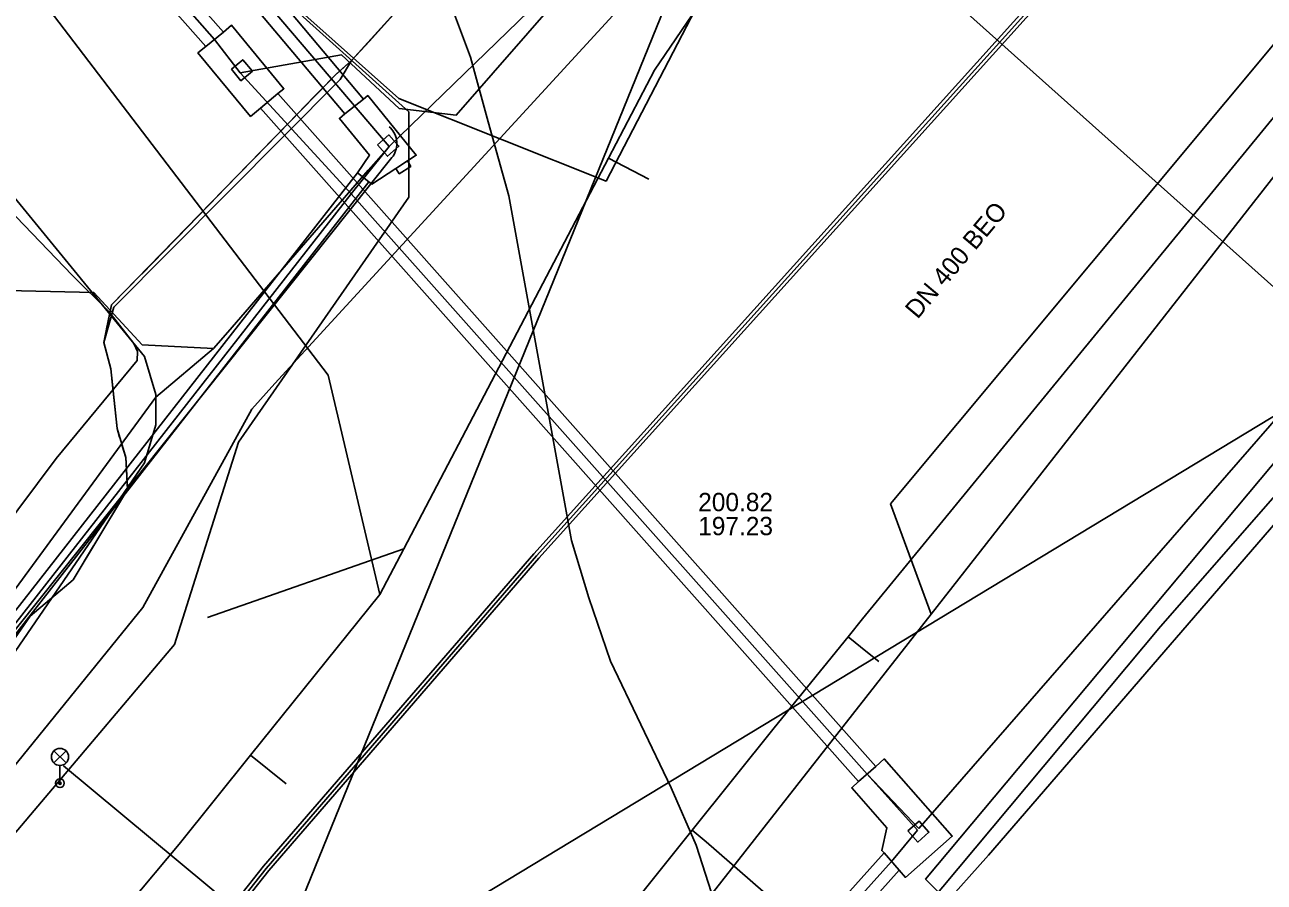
# Model space of a CAD drawing. Extents: x -598932 to -598196, y -1162210 to -1161504.
# Drawn here: x -598627.1 to -598572.9, y -1161789 to -1161751.5 of the extents above; entities that cross this region are included whole.
import ezdxf

# ---------------------------------------------------------------- set-up
doc = ezdxf.new("R2010")
doc.units = 0
for name, color, linetype in [('Vrstva 1', 7, 'Continuous'), ('Vrstva 10', 7, 'Continuous'), ('Vrstva 12', 7, 'Continuous'), ('Vrstva 13', 7, 'Continuous'), ('Vrstva 14', 7, 'Continuous'), ('Vrstva 16', 7, 'Continuous'), ('Vrstva 33', 7, 'Continuous'), ('Vrstva 4', 7, 'Continuous'), ('Vrstva 42', 7, 'Continuous'), ('Vrstva 44', 7, 'Continuous'), ('Vrstva 53', 7, 'Continuous'), ('Vrstva 54', 7, 'Continuous'), ('Vrstva 55', 7, 'Continuous'), ('Vrstva 58', 7, 'Continuous'), ('Vrstva 9', 7, 'Continuous')]:
    doc.layers.add(name, color=color, linetype=linetype)

msp = doc.modelspace()

# ---------------------------------------------------------------- linework, layer by layer
at = {"layer": 'Vrstva 1'}
for p, q in [((-598570.08, -1161749.41), (-598589.26, -1161772.42)), ((-598589.26, -1161772.42), (-598587.489, -1161777.24)), ((-598619.154, -1161777.396), (-598610.566, -1161774.388))]:
    msp.add_line(p, q, dxfattribs=at)
at = {"layer": 'Vrstva 10'}
for p, q in [((-598648.42, -1161711.89), (-598612.32, -1161754.71)), ((-598648.42, -1161711.89), (-598612.32, -1161754.71)), ((-598649.44, -1161712.32), (-598613.14, -1161755.36)), ((-598649.44, -1161712.32), (-598613.14, -1161755.36)), ((-598638.16, -1161729.41), (-598618.46, -1161751.78)), ((-598638.16, -1161729.41), (-598618.46, -1161751.78)), ((-598639.01, -1161729.96), (-598619.23, -1161752.41)), ((-598639.01, -1161729.96), (-598619.23, -1161752.41)), ((-598619.23, -1161752.41), (-598618.46, -1161751.78)), ((-598619.23, -1161752.41), (-598618.46, -1161751.78)), ((-598616.84, -1161755.11), (-598616.07, -1161754.47)), ((-598616.84, -1161755.11), (-598616.07, -1161754.47)), ((-598616.07, -1161754.47), (-598589.91, -1161783.91)), ((-598616.07, -1161754.47), (-598589.91, -1161783.91)), ((-598613.14, -1161755.36), (-598612.32, -1161754.71)), ((-598613.14, -1161755.36), (-598612.32, -1161754.71)), ((-598616.84, -1161755.11), (-598590.66, -1161784.57)), ((-598616.84, -1161755.11), (-598590.66, -1161784.57)), ((-598610.91, -1161757.75), (-598610.4, -1161757.42)), ((-598610.91, -1161757.75), (-598610.4, -1161757.42)), ((-598639.29, -1161792.09), (-598612.59, -1161757.94)), ((-598639.29, -1161792.09), (-598612.59, -1161757.94)), ((-598612.59, -1161757.94), (-598612.09, -1161758.33)), ((-598612.59, -1161757.94), (-598612.09, -1161758.33)), ((-598638.76, -1161792.44), (-598612.09, -1161758.33)), ((-598638.76, -1161792.44), (-598612.09, -1161758.33)), ((-598590.66, -1161784.57), (-598589.91, -1161783.91)), ((-598590.66, -1161784.57), (-598589.91, -1161783.91)), ((-598625.29, -1161827.53), (-598589.54, -1161787.69)), ((-598625.29, -1161827.53), (-598589.54, -1161787.69)), ((-598589.54, -1161787.69), (-598588.89, -1161788.45)), ((-598589.54, -1161787.69), (-598588.89, -1161788.45)), ((-598624.5, -1161828.14), (-598588.89, -1161788.45)), ((-598624.5, -1161828.14), (-598588.89, -1161788.45))]:
    msp.add_line(p, q, dxfattribs=at)
for points in [[(-598616.07, -1161754.47), (-598615.81, -1161754.26), (-598618.1, -1161751.48), (-598618.46, -1161751.78)], [(-598616.07, -1161754.47), (-598615.81, -1161754.26), (-598618.1, -1161751.48), (-598618.46, -1161751.78)], [(-598616.84, -1161755.11), (-598617.27, -1161755.47), (-598619.57, -1161752.69), (-598619.23, -1161752.41)], [(-598616.84, -1161755.11), (-598617.27, -1161755.47), (-598619.57, -1161752.69), (-598619.23, -1161752.41)], [(-598618.11, -1161753.41), (-598617.61, -1161752.99), (-598617.19, -1161753.49), (-598617.69, -1161753.91), (-598618.11, -1161753.41)], [(-598618.11, -1161753.41), (-598617.61, -1161752.99), (-598617.19, -1161753.49), (-598617.69, -1161753.91), (-598618.11, -1161753.41)], [(-598612.32, -1161754.71), (-598612.14, -1161754.56), (-598610.02, -1161757.17), (-598610.4, -1161757.42)], [(-598612.32, -1161754.71), (-598612.14, -1161754.56), (-598610.02, -1161757.17), (-598610.4, -1161757.42)], [(-598613.14, -1161755.36), (-598613.38, -1161755.56), (-598612.07, -1161757.17), (-598612.59, -1161757.94)], [(-598613.14, -1161755.36), (-598613.38, -1161755.56), (-598612.07, -1161757.17), (-598612.59, -1161757.94)], [(-598611.72, -1161756.72), (-598611.28, -1161757.21), (-598610.78, -1161756.77), (-598611.22, -1161756.28), (-598611.72, -1161756.72)], [(-598611.72, -1161756.72), (-598611.28, -1161757.21), (-598610.78, -1161756.77), (-598611.22, -1161756.28), (-598611.72, -1161756.72)], [(-598610.4, -1161757.42), (-598610.26, -1161757.66), (-598610.76, -1161757.98), (-598610.91, -1161757.75)], [(-598610.4, -1161757.42), (-598610.26, -1161757.66), (-598610.76, -1161757.98), (-598610.91, -1161757.75)], [(-598612.09, -1161758.33), (-598611.96, -1161758.43), (-598610.91, -1161757.75)], [(-598612.09, -1161758.33), (-598611.96, -1161758.43), (-598610.91, -1161757.75)], [(-598589.91, -1161783.91), (-598589.54, -1161783.58), (-598586.56, -1161786.96), (-598588.61, -1161788.76), (-598588.89, -1161788.45)], [(-598589.91, -1161783.91), (-598589.54, -1161783.58), (-598586.56, -1161786.96), (-598588.61, -1161788.76), (-598588.89, -1161788.45)], [(-598590.66, -1161784.57), (-598590.96, -1161784.84), (-598589.42, -1161786.6), (-598589.65, -1161787.59), (-598589.54, -1161787.69)], [(-598590.66, -1161784.57), (-598590.96, -1161784.84), (-598589.42, -1161786.6), (-598589.65, -1161787.59), (-598589.54, -1161787.69)], [(-598588.5, -1161786.73), (-598588.07, -1161787.22), (-598587.58, -1161786.79), (-598588.01, -1161786.3), (-598588.5, -1161786.73)], [(-598588.5, -1161786.73), (-598588.07, -1161787.22), (-598587.58, -1161786.79), (-598588.01, -1161786.3), (-598588.5, -1161786.73)]]:
    msp.add_lwpolyline(points, dxfattribs=at)
at = {"layer": 'Vrstva 12'}
for p, q in [((-598611.21, -1161756.79), (-598644.24, -1161717.96)), ((-598618.85, -1161752.1), (-598617.73, -1161753.57)), ((-598617.73, -1161753.57), (-598612.86, -1161758.86)), ((-598560.27, -1161754.79), (-598588.02, -1161786.62)), ((-598612.86, -1161758.86), (-598590.29, -1161784.24)), ((-598590.29, -1161784.24), (-598588.09, -1161786.7)), ((-598590.29, -1161784.24), (-598588.02, -1161786.62))]:
    msp.add_line(p, q, dxfattribs=at)
for points in [[(-598617.73, -1161753.57), (-598613.29, -1161752.78), (-598610.76, -1161755.12), (-598608.27, -1161755.41), (-598576.7, -1161719.3), (-598550.29, -1161690.77), (-598547.14, -1161687.36)], [(-598639.8, -1161728.29), (-598638.6, -1161729.7), (-598618.85, -1161752.1)], [(-598611.21, -1161756.79), (-598612.12, -1161757.82), (-598618.27, -1161764.91), (-598618.89, -1161765.62)], [(-598612.86, -1161758.86), (-598612.32, -1161758.18), (-598611.21, -1161756.79)], [(-598640.35, -1161794.18), (-598638.99, -1161792.25), (-598612.86, -1161758.86)], [(-598618.89, -1161765.62), (-598622.01, -1161765.47), (-598624.13, -1161763.18), (-598633.65, -1161762.95), (-598639.12, -1161764.44), (-598641.01, -1161764.25), (-598642.56, -1161765.55), (-598642.41, -1161767.52), (-598642.41, -1161775.34), (-598642.17, -1161790.19), (-598649.69, -1161797.54), (-598651.68, -1161795.52), (-598698.16, -1161842.5), (-598698.36, -1161842.27)], [(-598641.69, -1161795.86), (-598641.14, -1161794.65), (-598621.42, -1161767.75), (-598618.89, -1161765.62)], [(-598588.09, -1161786.7), (-598589.215, -1161788.07), (-598624.9, -1161827.84)]]:
    msp.add_lwpolyline(points, dxfattribs=at)
at = {"layer": 'Vrstva 13'}
msp.add_lwpolyline([(-598555.27, -1161753.75), (-598583.9, -1161729.43), (-598592.85, -1161739), (-598611.21, -1161756.79)], dxfattribs=at)
at = {"layer": 'Vrstva 14'}
msp.add_line((-598597.949, -1161786.696), (-598597.334, -1161787.209), dxfattribs=at)
for points in [[(-598597.949, -1161786.696), (-598594.355, -1161782.22), (-598591.124, -1161778.235), (-598590.488, -1161777.45), (-598568.259, -1161750.324), (-598540.145, -1161717.756), (-598494.895, -1161668.814), (-598474.946, -1161646.048), (-598446.726, -1161616.22), (-598420.512, -1161586.879), (-598391.532, -1161555.529), (-598341.416, -1161505.182)], [(-598589.947, -1161792.741), (-598577.445, -1161777.792), (-598565.596, -1161764.237), (-598559.546, -1161757.337), (-598558.635, -1161756.275), (-598558.918, -1161751.624), (-598555.314, -1161747.837), (-598550.53, -1161742.727), (-598537.985, -1161729.402), (-598525.355, -1161715.849), (-598512.719, -1161702.199), (-598500.184, -1161688.704), (-598495.944, -1161684.141), (-598496.644, -1161675.242), (-598493.647, -1161671.551), (-598491.273, -1161668.615), (-598474.912, -1161650.419), (-598466.442, -1161641.794), (-598445.99, -1161619.606), (-598438.518, -1161611.629), (-598437.483, -1161610.512)], [(-598714.198, -1161898.74), (-598714.06, -1161898.556), (-598710.961, -1161889.776), (-598709.348, -1161885.209), (-598692.94, -1161864.74), (-598688.776, -1161860.738), (-598685, -1161855.44), (-598662.12, -1161826.49), (-598647.66, -1161808.72), (-598629.293, -1161785.959), (-598621.98, -1161776.96), (-598617.208, -1161768.282), (-598616.2, -1161767.15), (-598599.603, -1161749.072), (-598591.333, -1161740.194), (-598580.26, -1161728.311)], [(-598591.124, -1161778.235), (-598590.275, -1161778.926), (-598589.772, -1161779.324)], [(-598597.949, -1161786.696), (-598602.338, -1161792.178), (-598603.707, -1161793.87)], [(-598597.334, -1161787.209), (-598590.41, -1161793.23), (-598589.947, -1161792.741)]]:
    msp.add_lwpolyline(points, dxfattribs=at)
at = {"layer": 'Vrstva 16'}
msp.add_lwpolyline([(-598560.67, -1161752.75), (-598557.52, -1161756.02), (-598568.8, -1161769.07), (-598584.98, -1161787.79), (-598587.03, -1161790.09), (-598589.52, -1161793.04), (-598597.01, -1161801.89), (-598611.83, -1161819.43), (-598616.42, -1161824.71), (-598624.01, -1161833.48), (-598624.6, -1161833.51)], dxfattribs=at)
at = {"layer": 'Vrstva 33'}
for p, q in [((-598625.874, -1161783.227), (-598625.344, -1161783.757)), ((-598625.874, -1161783.757), (-598625.344, -1161783.227)), ((-598625.609, -1161784.642), (-598625.609, -1161783.867))]:
    msp.add_line(p, q, dxfattribs=at)
for centre, radius in [((-598625.609, -1161783.492), 0.375), ((-598625.609, -1161784.642), 0.19), ((-598625.609, -1161784.642), 0.05)]:
    msp.add_circle(centre, radius, dxfattribs=at)
at = {"layer": 'Vrstva 42'}
msp.add_line((-598640.42, -1161794.02), (-598611.08, -1161757.27), dxfattribs=at)
for points in [[(-598482.625, -1161640.144), (-598482.467, -1161640.638), (-598493.794, -1161653.11), (-598495.271, -1161654.682), (-598509.79, -1161670.452), (-598509.789, -1161670.451), (-598514.544, -1161675.66), (-598514.586, -1161675.706), (-598563.469, -1161729.131), (-598604.648, -1161774.799), (-598616.464, -1161788.466), (-598628.603, -1161803.794)], [(-598628.837, -1161803.606), (-598616.696, -1161788.274), (-598604.872, -1161774.601), (-598563.691, -1161728.929), (-598514.958, -1161675.668), (-598514.766, -1161675.458), (-598510.011, -1161670.249), (-598510.01, -1161670.248), (-598495.509, -1161654.498), (-598494.886, -1161653.538)], [(-598628.837, -1161803.606), (-598616.696, -1161788.274), (-598604.872, -1161774.601), (-598563.691, -1161728.929), (-598514.958, -1161675.668), (-598514.766, -1161675.458), (-598510.011, -1161670.249), (-598510.01, -1161670.248), (-598495.509, -1161654.498), (-598494.886, -1161653.538)], [(-598722.434, -1161887.506), (-598721.303, -1161887.465), (-598711.981, -1161877.933), (-598701.016, -1161865.728), (-598698.292, -1161862.397), (-598697.293, -1161861.83), (-598689.452, -1161859.77), (-598688.12, -1161859.789), (-598687.331, -1161860.531), (-598681.484, -1161865.606), (-598680.195, -1161866.255), (-598678.811, -1161865.236), (-598675.692, -1161860.773), (-598673.236, -1161858.028), (-598665.054, -1161848.125), (-598640.034, -1161817.645), (-598628.603, -1161803.794), (-598616.464, -1161788.466), (-598604.648, -1161774.799), (-598563.469, -1161729.131), (-598514.586, -1161675.706), (-598514.881, -1161675.495)], [(-598514.841, -1161675.57), (-598514.772, -1161675.687), (-598563.58, -1161729.03), (-598604.76, -1161774.7), (-598616.58, -1161788.37), (-598628.72, -1161803.7), (-598640.15, -1161817.55), (-598650.17, -1161829.78), (-598665.17, -1161848.03), (-598673.35, -1161857.93), (-598675.81, -1161860.68), (-598678.92, -1161865.13), (-598680.21, -1161866.08), (-598681.4, -1161865.48), (-598687.23, -1161860.42), (-598688.06, -1161859.64), (-598689.47, -1161859.62), (-598697.35, -1161861.69), (-598698.39, -1161862.28), (-598701.13, -1161865.63), (-598712.09, -1161877.83), (-598721.41, -1161887.36)], [(-598611.08, -1161757.27), (-598611.031, -1161757.203), (-598610.988, -1161757.131), (-598610.951, -1161757.057), (-598610.92, -1161756.979), (-598610.896, -1161756.9), (-598610.88, -1161756.818), (-598610.87, -1161756.735), (-598610.867, -1161756.652), (-598610.872, -1161756.569), (-598610.883, -1161756.486), (-598610.902, -1161756.405), (-598610.927, -1161756.326), (-598610.959, -1161756.249), (-598610.998, -1161756.175), (-598611.042, -1161756.104), (-598611.093, -1161756.038), (-598611.149, -1161755.977), (-598611.21, -1161755.92)]]:
    msp.add_lwpolyline(points, dxfattribs=at)
at = {"layer": 'Vrstva 44'}
msp.add_lwpolyline([(-598629.97, -1161776.02), (-598625.78, -1161770.44), (-598622.23, -1161766.15), (-598622.22, -1161765.76), (-598622.38, -1161765.41), (-598623.47, -1161764), (-598625.08, -1161762.41), (-598628.94, -1161758.4)], dxfattribs=at)
at = {"layer": 'Vrstva 53'}
for points in [[(-598609.61, -1161747.61), (-598607.64, -1161752.88), (-598606.87, -1161755.71), (-598605.97, -1161758.94), (-598603.23, -1161774.02), (-598602.46, -1161776.53), (-598601.52, -1161779.31), (-598598.86, -1161784.84), (-598597.77, -1161787.35), (-598596.71, -1161790.67), (-598595.79, -1161793.54), (-598594.83, -1161796.22), (-598593.94, -1161799.41), (-598592.99, -1161801.85), (-598591.22, -1161806.87), (-598589.7, -1161809.75), (-598588.76, -1161814.1), (-598588.73, -1161814.4)], [(-598609.841, -1161749.701), (-598612.07, -1161752.18), (-598612.85, -1161753.03), (-598613.52, -1161753.62), (-598623.35, -1161763.72), (-598623.69, -1161765.36), (-598623.39, -1161766.52), (-598623.11, -1161769.13), (-598622.73, -1161770.39), (-598622.65, -1161771.79), (-598625.03, -1161775.74), (-598626.92, -1161777.34), (-598629.01, -1161780.33), (-598632.04, -1161785.05), (-598632.43, -1161785.95), (-598634.19, -1161788.81), (-598640.81, -1161797.29)]]:
    msp.add_lwpolyline(points, dxfattribs=at)
at = {"layer": 'Vrstva 54'}
for p, q in [((-598568.721, -1161766.31), (-598595.679, -1161742.213)), ((-598600.402, -1161804.695), (-598625.45, -1161783.876))]:
    msp.add_line(p, q, dxfattribs=at)
for points in [[(-598687.821, -1161859.742), (-598647.718, -1161830.151), (-598630.44, -1161809.067), (-598615.881, -1161791.862), (-598595.724, -1161742.271)], [(-598663.206, -1161879.566), (-598645.593, -1161831.834), (-598628.289, -1161810.908), (-598613.766, -1161793.569), (-598568.721, -1161766.31)]]:
    msp.add_lwpolyline(points, dxfattribs=at)
at = {"layer": 'Vrstva 55'}
for points in [[(-598593.724, -1161815.599), (-598601.79, -1161825.2), (-598612.66, -1161816.58), (-598605.21, -1161808.89), (-598597.75, -1161800.73), (-598596.12, -1161801.43), (-598593.55, -1161803.29), (-598583.76, -1161792.8), (-598587.73, -1161788.84), (-598556.49, -1161751.54), (-598543.66, -1161733.82), (-598504.5, -1161691.15), (-598500.07, -1161684.86), (-598483.28, -1161665.74), (-598469.525, -1161651.138), (-598469.135, -1161651.28), (-598469.525, -1161651.138), (-598431.76, -1161609.32), (-598365.821, -1161539.037), (-598342.93, -1161515.615), (-598331.661, -1161505.182)], [(-598687.9, -1161859.88), (-598687.665, -1161860.067), (-598686.34, -1161858.55), (-598665.36, -1161832.2), (-598647.88, -1161811.69), (-598632.26, -1161792.34), (-598620.6, -1161778.58), (-598617.8, -1161769.72), (-598610.34, -1161759), (-598610.34, -1161755.27), (-598623.936, -1161743.039), (-598634.82, -1161725.89), (-598648.11, -1161713.3), (-598648.437, -1161712.771), (-598653, -1161709.34), (-598656.27, -1161705.61), (-598668.62, -1161681.83), (-598671.66, -1161674.83), (-598683.11, -1161642.61), (-598670.09, -1161637.1), (-598667.406, -1161636.169), (-598667.557, -1161635.626)], [(-598593.724, -1161815.599), (-598601.79, -1161825.2), (-598612.66, -1161816.58), (-598614.54, -1161818.45), (-598638.67, -1161800.34), (-598641.16, -1161798.68), (-598621.91, -1161770.62), (-598621.41, -1161768.96), (-598621.41, -1161767.63), (-598621.91, -1161765.97), (-598661.59, -1161717.49), (-598653.12, -1161709.36), (-598656.44, -1161705.37), (-598668.39, -1161682.46), (-598671.71, -1161674.66), (-598683.11, -1161642.61), (-598670.09, -1161637.1), (-598667.406, -1161636.169), (-598667.557, -1161635.626)], [(-598635.02, -1161725.8), (-598623.513, -1161743.463), (-598608.12, -1161722.98), (-598608.22, -1161717.163), (-598608.12, -1161722.98), (-598623.249, -1161743.568), (-598610.78, -1161754.69), (-598601.71, -1161758.3), (-598595.65, -1161746.64), (-598593.576, -1161744.441), (-598595.719, -1161742.325), (-598593.576, -1161744.441), (-598591.036, -1161741.822), (-598575.14, -1161725.19), (-598564.458, -1161715.417), (-598553.451, -1161703.881), (-598547.789, -1161697.531), (-598546.625, -1161695.044), (-598548.56, -1161692.55), (-598559.49, -1161681.15), (-598556.019, -1161677.263), (-598556.805, -1161676.476)]]:
    msp.add_lwpolyline(points, dxfattribs=at)
at = {"layer": 'Vrstva 58'}
for p, q in [((-598610.196, -1161750.093), (-598612.85, -1161753.03)), ((-598612.85, -1161753.03), (-598611.685, -1161751.741)), ((-598613.52, -1161753.62), (-598612.85, -1161753.03)), ((-598612.85, -1161753.03), (-598613.482, -1161753.586)), ((-598615.033, -1161755.175), (-598613.52, -1161753.62)), ((-598613.763, -1161753.87), (-598615.045, -1161755.186)), ((-598618.392, -1161758.626), (-598615.045, -1161755.186)), ((-598615.045, -1161755.186), (-598617.111, -1161757.31)), ((-598617.122, -1161757.321), (-598618.392, -1161758.626)), ((-598622.019, -1161762.353), (-598618.671, -1161758.913)), ((-598618.671, -1161758.913), (-598620.47, -1161760.761)), ((-598618.392, -1161758.626), (-598618.671, -1161758.913)), ((-598620.749, -1161761.048), (-598622.019, -1161762.353)), ((-598622.019, -1161762.353), (-598622.03, -1161762.364)), ((-598623.35, -1161763.72), (-598622.03, -1161762.364)), ((-598622.03, -1161762.364), (-598623.35, -1161763.72)), ((-598623.69, -1161765.36), (-598623.35, -1161763.72)), ((-598623.35, -1161763.72), (-598623.567, -1161764.768)), ((-598623.571, -1161764.784), (-598623.69, -1161765.36)), ((-598623.39, -1161766.52), (-598623.69, -1161765.36)), ((-598623.69, -1161765.36), (-598623.39, -1161766.52)), ((-598623.39, -1161766.52), (-598623.11, -1161769.13)), ((-598623.11, -1161769.13), (-598623.344, -1161766.952)), ((-598622.73, -1161770.39), (-598623.11, -1161769.13)), ((-598623.11, -1161769.13), (-598622.998, -1161769.502)), ((-598622.882, -1161769.885), (-598622.73, -1161770.39)), ((-598622.656, -1161771.682), (-598622.73, -1161770.39)), ((-598622.73, -1161770.39), (-598622.65, -1161771.79)), ((-598625.03, -1161775.74), (-598622.65, -1161771.79)), ((-598622.65, -1161771.79), (-598624.131, -1161774.249)), ((-598622.65, -1161771.79), (-598622.655, -1161771.698)), ((-598624.14, -1161774.262), (-598625.03, -1161775.74)), ((-598625.03, -1161775.74), (-598625.408, -1161776.06)), ((-598625.103, -1161775.802), (-598625.03, -1161775.74)), ((-598626.92, -1161777.34), (-598625.408, -1161776.06)), ((-598625.408, -1161776.06), (-598626.92, -1161777.34)), ((-598628.535, -1161779.651), (-598626.92, -1161777.34)), ((-598626.92, -1161777.34), (-598627.263, -1161777.831))]:
    msp.add_line(p, q, dxfattribs=at)
for points in [[(-598623.69, -1161765.36), (-598623.26, -1161763.82), (-598613.35, -1161753.86), (-598612.85, -1161753.03), (-598612.07, -1161752.18), (-598609.84, -1161749.7), (-598609.6, -1161747.86), (-598611.05, -1161744.13), (-598612.89, -1161741.88), (-598617.68, -1161737.76), (-598618.91, -1161736.88), (-598619.66, -1161736.35), (-598631.7, -1161727.81)], [(-598623.69, -1161765.36), (-598623.35, -1161763.72), (-598613.52, -1161753.62), (-598612.85, -1161753.03), (-598612.07, -1161752.18), (-598609.84, -1161749.7), (-598609.6, -1161747.86), (-598611.05, -1161744.13), (-598612.89, -1161741.88), (-598617.68, -1161737.76), (-598618.91, -1161736.88), (-598619.66, -1161736.35), (-598631.7, -1161727.81)], [(-598628.535, -1161779.651), (-598626.92, -1161777.34), (-598625.408, -1161776.06), (-598625.03, -1161775.74), (-598622.65, -1161771.79), (-598622.73, -1161770.39), (-598623.11, -1161769.13), (-598623.39, -1161766.52), (-598623.69, -1161765.36), (-598623.35, -1161763.72), (-598613.52, -1161753.62), (-598612.85, -1161753.03), (-598609.84, -1161749.7), (-598609.6, -1161747.86), (-598611.05, -1161744.13), (-598612.89, -1161741.88), (-598615.696, -1161739.467), (-598617.68, -1161737.76), (-598619.66, -1161736.35), (-598631.7, -1161727.81)], [(-598609.84, -1161749.7), (-598612.85, -1161753.03), (-598613.52, -1161753.62), (-598615.045, -1161755.186), (-598618.392, -1161758.626), (-598618.671, -1161758.913), (-598622.019, -1161762.353), (-598622.03, -1161762.364), (-598623.35, -1161763.72), (-598623.69, -1161765.36), (-598623.39, -1161766.52), (-598623.11, -1161769.13), (-598622.73, -1161770.39), (-598622.65, -1161771.79), (-598625.03, -1161775.74), (-598625.408, -1161776.06), (-598626.92, -1161777.34), (-598629.01, -1161780.33)], [(-598669.89, -1161829.37), (-598668.06, -1161829.56), (-598667.17, -1161828.81), (-598664.51, -1161824.98), (-598658.48, -1161816.94), (-598652.34, -1161809.41), (-598646.32, -1161801.61), (-598643.47, -1161798.47), (-598640.81, -1161797.29), (-598634.19, -1161788.81), (-598632.43, -1161785.95), (-598632.04, -1161785.05), (-598629.01, -1161780.33), (-598626.92, -1161777.34), (-598625.03, -1161775.74), (-598622.65, -1161771.79), (-598622.73, -1161770.39), (-598623.11, -1161769.13), (-598623.39, -1161766.52), (-598623.69, -1161765.36)], [(-598640.81, -1161797.29), (-598634.19, -1161788.81), (-598632.43, -1161785.95), (-598632.04, -1161785.05), (-598629.01, -1161780.33), (-598626.92, -1161777.34), (-598625.03, -1161775.74), (-598622.65, -1161771.79), (-598622.73, -1161770.39), (-598623.11, -1161769.13), (-598623.39, -1161766.52), (-598623.69, -1161765.36)]]:
    msp.add_lwpolyline(points, dxfattribs=at)
at = {"layer": 'Vrstva 9'}
for p, q in [((-598632.98, -1161741.74), (-598613.88, -1161766.79)), ((-598599.837, -1161758.221), (-598601.609, -1161757.293)), ((-598572.43, -1161758.03), (-598587.489, -1161777.24)), ((-598613.88, -1161766.79), (-598611.61, -1161776.38)), ((-598587.489, -1161777.24), (-598605.48, -1161800.19)), ((-598615.708, -1161784.667), (-598617.267, -1161783.414))]:
    msp.add_line(p, q, dxfattribs=at)
for points in [[(-598585.65, -1161732.96), (-598586.944, -1161734.861), (-598589.015, -1161737.903), (-598599.59, -1161753.44)], [(-598599.59, -1161753.44), (-598601.609, -1161757.293), (-598610.566, -1161774.388), (-598611.61, -1161776.38)], [(-598611.61, -1161776.38), (-598617.267, -1161783.414), (-598620.4, -1161787.31)], [(-598620.4, -1161787.31), (-598624.734, -1161792.498), (-598637.962, -1161808.329), (-598649.33, -1161821.935), (-598650.336, -1161823.139)]]:
    msp.add_lwpolyline(points, dxfattribs=at)

# ---------------------------------------------------------------- texts
at = {"layer": 'Vrstva 4'}
msp.add_text('DN 400 BEO', height=0.8, rotation=50, dxfattribs=at).set_placement((-598588.08, -1161764.371))
for s, p in [('200.82', (-598597.679, -1161772.741)), ('197.23', (-598597.679, -1161773.791))]:
    msp.add_text(s, height=0.8, dxfattribs=at).set_placement(p)

doc.saveas('drawing.dxf')
